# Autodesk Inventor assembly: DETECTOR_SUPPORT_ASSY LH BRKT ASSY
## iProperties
Shininess: 64.0
Length Units: 11272
Angle Units: 11279
Time Units: 11290
Mass Units: 11286
Length Display Precision: 3
Angle Display Precision: 2
Compacted: True
Part Number: DETECTOR_SUPPORT_ASSY LH BRKT ASSY
Document SubType Name: Assembly
Created: 2004-08
Designer: John Blackburn
Manufacturer: Standard
Standards Organization: Custom
Density: 0.0
Volumn: 0.0
Area: 0.0
PropertySet Name: Model Information
Control State: 0
Master: False
Checked Out: False
Author: John Blackburn
